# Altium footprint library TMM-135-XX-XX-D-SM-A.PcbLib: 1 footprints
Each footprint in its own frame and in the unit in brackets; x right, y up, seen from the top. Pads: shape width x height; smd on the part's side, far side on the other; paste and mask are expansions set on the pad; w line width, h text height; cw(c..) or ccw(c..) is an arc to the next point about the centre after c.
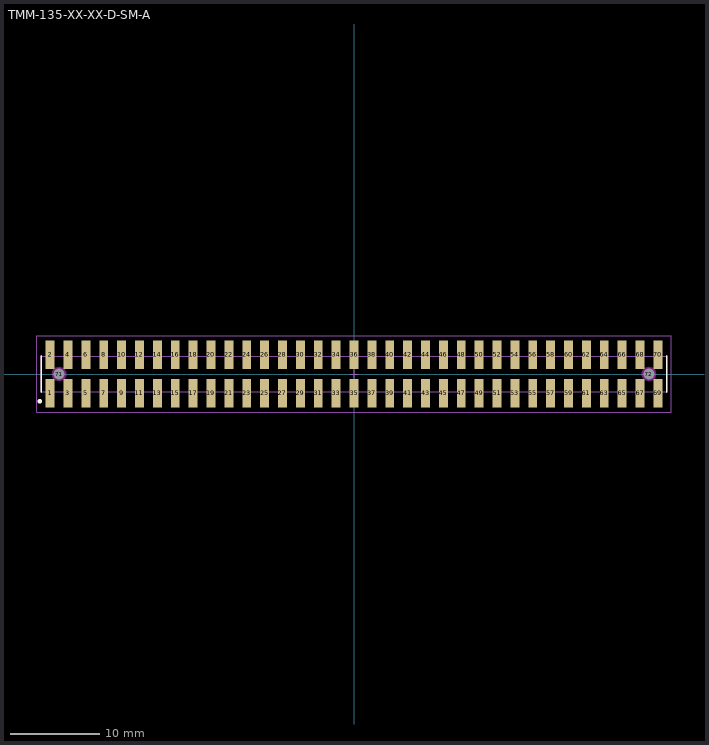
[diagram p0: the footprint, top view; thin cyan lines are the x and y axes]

## TMM-135-XX-XX-D-SM-A [mm] "2.00mm pitch, 70 pin, terminal strip; double row, w/alignment pins, SMT"
height 2.77
pads (72):
  rect 1x3.2 smd mask+0: 1(-34,-2.15) 2(-34,2.15) 3(-32,-2.15) 4(-32,2.15) 5(-30,-2.15) 6(-30,2.15) 7(-28,-2.15) 8(-28,2.15) 9(-26,-2.15) 10(-26,2.15) 11(-24,-2.15) 12(-24,2.15) 13(-22,-2.15) 14(-22,2.15) 15(-20,-2.15) 16(-20,2.15) 17(-18,-2.15) 18(-18,2.15) 19(-16,-2.15) 20(-16,2.15) 21(-14,-2.15) 22(-14,2.15) 23(-12,-2.15) 24(-12,2.15) 25(-10,-2.15) 26(-10,2.15) 27(-8,-2.15) 28(-8,2.15) 29(-6,-2.15) 30(-6,2.15) 31(-4,-2.15) 32(-4,2.15) 33(-2,-2.15) 34(-2,2.15) 35(0,-2.15) 36(0,2.15) 37(2,-2.15) 38(2,2.15) 39(4,-2.15) 40(4,2.15) 41(6,-2.15) 42(6,2.15) 43(8,-2.15) 44(8,2.15) 45(10,-2.15) 46(10,2.15) 47(12,-2.15) 48(12,2.15) 49(14,-2.15) 50(14,2.15) 51(16,-2.15) 52(16,2.15) 53(18,-2.15) 54(18,2.15) 55(20,-2.15) 56(20,2.15) 57(22,-2.15) 58(22,2.15) 59(24,-2.15) 60(24,2.15) 61(26,-2.15) 62(26,2.15) 63(28,-2.15) 64(28,2.15) 65(30,-2.15) 66(30,2.15) 67(32,-2.15) 68(32,2.15) 69(34,-2.15) 70(34,2.15)
  round 1 hole 1.2 unplated mask+0: 71(-33,0) 72(33,0)
Top Overlay:
  circle w0.25: c-35.15,-3.05 r0.125
  lines w0.2: -35,-2 -35,2 ; 35,-2 35,2
Keep-Out Layer:
  pour cut-out: -32.193,0 -32.22,0.209 -32.301,0.403 -32.429,0.571 -32.596,0.699 -32.791,0.779 -33,0.807 -33.209,0.779 -33.403,0.699 -33.57,0.571 -33.699,0.403 -33.779,0.209 -33.807,0 -33.779,-0.209 -33.699,-0.403 -33.57,-0.571 -33.403,-0.699 -33.209,-0.779 -33,-0.807 -32.791,-0.779 -32.596,-0.699 -32.429,-0.571 -32.301,-0.403 -32.22,-0.209
  pour cut-out: 33.807,0 33.779,0.209 33.699,0.403 33.57,0.571 33.403,0.699 33.209,0.779 33,0.807 32.791,0.779 32.596,0.699 32.429,0.571 32.301,0.403 32.22,0.209 32.193,0 32.22,-0.209 32.301,-0.403 32.429,-0.571 32.596,-0.699 32.791,-0.779 33,-0.807 33.209,-0.779 33.403,-0.699 33.57,-0.571 33.699,-0.403 33.779,-0.209
Mechanical 12:
  lines w0.001: -35,-2 35,-2 35,2 -35,2 -35,-2
Mechanical 13:
  lines w0.1: -35,-2 35,-2 35,2 -35,2 -35,-2
  text ".Designator" at 0,-0.127 h1.52
Mechanical 15:
  lines w0.05: -0.5,0 0.5,0 ; 0,-0.5 0,0.5 ; -35.5,-4.3 35.5,-4.3 35.5,4.3 -35.5,4.3 -35.5,-4.3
